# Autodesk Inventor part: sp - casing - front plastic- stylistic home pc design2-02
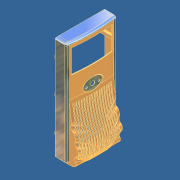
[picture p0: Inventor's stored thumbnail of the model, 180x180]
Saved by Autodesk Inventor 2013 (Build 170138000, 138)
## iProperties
Company: Autodesk Inc.
Created: 2005-12
Part Number: sp - casing - front plastic- stylistic home pc design2-02
Document SubType Name: Modeling
Designer: Autodesk Inc.
Stock Number: sp - casing - front plastic
Density: 1 g/cm^3
Mass: 300.417 g
Surface Area: 2156.89 cm^2
Volume: 300.417 cm^3
Material: Allgemein
Title: PC Demo
Author: Autodesk Inc.
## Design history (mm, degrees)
sketch "Sketch3"
  geometry: L1 (-90, 370)-(-79, 370); L2 (-79, 370)-(-79, 0); L3 (-79, 0)-(-90, 0); L4 (-90, 0)-(-90, 370); 2 further points
  constraints: 8 end point, 2 parallel, 1 coincident, 1 horizontal, 1 perpendicular
  dimensions: "d10" = 11 distance between parallel lines of L4 L2
extrude "Extrusion2" new body sketch "Sketch3" distance "d11" = 40; taper "d12" = 0 deg
mirror "Mirror1"
sketch "Sketch4"
  geometry: L1 (0, 11)-(40, 11) reference; L2 (0, 169)-(40, 169) reference; L3 (0, 169)-(0, 11); L4 (0, 180)-(40, 180) reference; L5 (40, 180)-(40, 169) reference; A1 r 600 centre (-554.776, 90) between (40, 11) and (40, 169)
  constraints: 2 end point, 2 point on circle, 1 centre point, 1 perpendicular
  dimensions: "d15" = 600 radius of A1
extrude "Extrusion3" join sketch "Sketch4" distance "d17" = 380 (computed from HEIGHT); taper "d18" = 0 deg
feature "FaceDraft7" dims angle "d20" = 10 deg
feature "FaceDraft8" dims angle "d21" = 10 deg
node "demo1"
sketch "Sketch10"
  geometry: L1 (203.5, 22.5)-(203.004, 22.434); L2 (203.004, 22.434)-(204.088, 14.307); L3 (204.088, -14.307)-(204.584, -14.373); L4 (206.5, 0)-(203.5, -22.5); L5 (204.584, -14.373)-(203.5, -22.5); L6 (203.004, -22.434)-(204.088, -14.307); L7 (203.5, -22.5)-(203.004, -22.434); L8 (204.584, 14.373)-(203.5, 22.5); L9 (204.088, 14.307)-(204.584, 14.373); L10 (206.5, 0)-(203.5, 22.5); C1 r 4 at (203.5, 22.5); C2 r 7.5 at (206.5, 0); C3 r 4 at (203.5, -22.5); C4 r 15 at (206.5, 0); A1 r 14.5 centre (206.5, 0) between (204.584, 14.373) and (204.584, -14.373)
  constraints: 20 end point, 5 centre point, 2 coincident, 2 point on circle, 2 point on line
workaxis "Work Axis1"
workplane "Work Plane4"
workplane "Work Plane5"
sketch "Sketch40"
  geometry: L1 (-45.224, 370)-(-45.224, -10) reference; L2 (-396, -52)-(0, -52) reference; L3 (-40, -10)-(-45.224, -10) reference; A1 r 333.146 centre (-378.319, 197.496) between (-69.011, 73.744) and (-45.224, 191.715); 1 further point
  constraints: 2 point on circle, 1 centre point, 1 horizontal, 1 point on line, 4 other
  dimensions: "d311" = 30.18241 horizontal distance of L1.end point (-75.406, 29.235); "d312" = 39.2354 vertical distance of L1.end point (-75.406, 29.235)
sketch "3D Sketch2"
  node "Project to Surface2"
sketch "3D Sketch3"
feature "SweepSrf2" dims "d255" = 0
feature "Extend3" dims "d256" = 80
feature "Extend4" dims "d257" = 80
feature "Sculpt2"
sketch "Sketch49" dims "d315" = 10
  geometry: L1 (191.715, 79)-(0, 79) reference; L2 (191.715, -79)-(0, -79) reference; L3 (-88.757, 0)-(446.459, 0) reference; 7 further points; 6 other entities
  constraints: 12 other
  dimensions: "d314" = 45 distance of point (108.452, 79) point (63.452, 79)
sketch "3D Sketch5"
  node "Project to Surface3"
sketch "Sketch50"
  geometry: A1 r 13.5 centre (57.483, 119.87) between (49.065, 130.425) and (55.768, 106.479); A2 r 14.055 centre (73.113, 75.347) between (63.316, 85.425) and (70.829, 61.479); A3 r 12.289 centre (71.124, 28.15) between (70.517, 40.425) and (67.276, 16.479); 1 further point
  constraints: 6 point on circle, 3 centre point
feature "Sculpt4"
feature "LoftSrf3" dims "d300" = 0, "d301" = 90 deg, "d302" = 0, "d303" = 90 deg
feature "LoftSrf4" dims "d304" = 0, "d305" = 90 deg, "d306" = 0, "d307" = 90 deg
feature "Sculpt5"
feature "Sculpt6"
mirror "Mirror6"
fillet "Fillet21" dims "d309" = 10
feature "FaceDraft12" dims angle "d281" = 2 deg
fillet "Fillet19" dims "d284" = 8
split "Split6"
shell "Shell7" dims "d279" = 3
fillet "Fillet20" dims "d286" = 5
sketch "Sketch11"
  geometry: L1 (-321.8, 0)-(485.3, 0) reference; L2 (0, -183.769)-(0, 183.769) reference; L3 (176.5, -2.5)-(11.5, -2.5); L4 (11.5, -2.5)-(11.5, -6.5); L5 (11.5, -6.5)-(176.5, -6.5); L6 (176.5, -6.5)-(176.5, -2.5); 2 further points
  constraints: 8 end point, 1 other
extrude "Extrusion14" cut sketch "Sketch11" distance "d114" = 375 (computed from HEIGHT); taper "d115" = 0 deg
pattern_linear "Rectangular Pattern4" dims "d118" = 9 (= 0.05 x WIDTH)
mirror "Mirror3"
workplane "Work Plane11"
sketch "Sketch14"
  geometry: L1 (308, 73)-(350, 73); L2 (350, 73)-(350, -73); L3 (350, -73)-(308, -73); L4 (308, -73)-(308, 73); L5 (370, 77.779)-(370, -77.779) reference; 2 further points
  constraints: 8 end point, 2 midpoint, 2 parallel, 1 horizontal, 1 horizontal alignment, 1 perpendicular
  dimensions: "d319" = 146 distance of L1.end L2.end; "d320" = 42 distance of L1.start L1.end; "d321" = 20 distance between parallel lines of L5 L2
extrude "Extrusion16" cut sketch "Sketch14" stored distance "d126" = 20; taper "d127" = 0 deg
pattern_linear "Rectangular Pattern5" dims "d130" = 42
feature "Sculpt3"
extrude "Extrusion18" cut sketch "Sketch10" stored distance "d168" = 10; taper "d169" = 0 deg
fillet "Fillet12" dims "d142" = 2
sketch "Sketch24"
  geometry: L1 (307.5, -87)-(297.5, -87); L2 (297.5, -87)-(297.5, -78.5); L3 (297.5, -78.5)-(307.5, -78.5); L4 (307.5, -78.5)-(307.5, -87); L5 (61, -87)-(71, -87); L6 (71, -87)-(71, -78.5); L7 (71, -78.5)-(61, -78.5); L8 (61, -78.5)-(61, -87); L9 (369, -89)-(369, 89); L10 (66, -78.5)-(66, -75.023); L11 (302.5, -78.5)-(302.5, -75.864); L12 (180, -87)-(190, -87); L13 (190, -87)-(190, -78.5); L14 (190, -78.5)-(180, -78.5); L15 (180, -78.5)-(180, -87); L16 (185, -78.5)-(185, -69.605); L17 (1, -47.752)-(1, -67.512); L18 (366.998, -87)-(3, -87); L19 (366.998, 87)-(366.998, 77.779) reference; L20 (366.998, 77.779)-(366.998, -77.779) reference; L21 (366.998, -77.779)-(366.998, -87) reference; L22 (366.998, -87)-(3, -87) reference; L23 (3, -87)-(3, -76) reference; L24 (3, -76)-(-7, -76) reference; L25 (-7, -76)-(-7, 76) reference; L26 (-7, 76)-(3, 76) reference; L27 (3, 76)-(3, 87) reference; L28 (3, 87)-(366.998, 87) reference; L29 (0, 79)-(0, 88) reference; L30 (0, 79)-(-10, 79) reference; L31 (-10, 79)-(-10, -79) reference; L32 (0, -79)-(-10, -79) reference; L33 (0, -79)-(0, -88) reference; L34 (2, -90)-(364.997, -90) reference; L35 (370, -77.779)-(370, -85) reference; L36 (370, 77.779)-(370, -77.779) reference; L37 (370, 85)-(370, 77.779) reference; L38 (2, 90)-(364.997, 90) reference; A1 r 2 centre (2, 88) between (2, 90) and (0, 88) reference; A2 r 2 centre (2, -88) between (0, -88) and (2, -90) reference; 2 further points
  constraints: 36 end point, 10 parallel, 5 midpoint, 3 equal length, 3 horizontal, 3 perpendicular, 2 horizontal alignment, 1 collinear, 2 other
  dimensions: "d188" = 368 distance between parallel lines of L9 L17 (derived); "d189" = 184 distance between parallel lines of L16 L17 (derived); "d190" = 10 distance of L2.end L3.end; "d191" = 8.5 distance of L12.end L13.end; "d194" = 65 distance from line of L10.end L17; "d195" = 66.5 distance between parallel lines of L11 L9
extrude "Extrusion21" join sketch "Sketch24" stored distance "d192" = 20; taper "d193" = 0 deg
mirror "Mirror4"
sketch "Sketch25"
  geometry: L1 (71, 176)-(71, 78.5) reference; L2 (190, 176)-(190, 78.5) reference; L3 (307.5, 176)-(307.5, 78.5) reference; L4 (297.5, 78.5)-(307.5, 78.5); L5 (307.5, 78.5)-(307.5, 82); L6 (307.5, 82)-(297.5, 82); L7 (297.5, 82)-(297.5, 78.5); L8 (180, 78.5)-(190, 78.5); L9 (190, 78.5)-(190, 82); L10 (190, 82)-(180, 82); L11 (180, 82)-(180, 78.5); L12 (61, 78.5)-(71, 78.5); L13 (71, 78.5)-(71, 82); L14 (71, 82)-(61, 82); L15 (61, 82)-(61, 78.5)
  constraints: 24 end point, 6 parallel, 3 horizontal, 3 perpendicular, 3 point on line, 2 collinear
  dimensions: "d197" = 3.5 distance between parallel lines of L4 L6
extrude "Extrusion22" join sketch "Sketch25" distance "d198" = 10; taper "d199" = 0 deg
sketch "Sketch32"
  geometry: L1 (307.5, 2)-(307.5, -78.5) reference; L2 (307.5, -78.5)-(297.5, -78.5) reference; L3 (190, 2)-(190, -78.5) reference; L4 (71, 2)-(71, -78.5) reference; L5 (297.5, -78.5)-(307.5, -78.5); L6 (307.5, -78.5)-(307.5, -82); L7 (307.5, -82)-(297.5, -82); L8 (297.5, -82)-(297.5, -78.5); L9 (180, -78.5)-(190, -78.5); L10 (190, -78.5)-(190, -82); L11 (190, -82)-(180, -82); L12 (180, -82)-(180, -78.5); L13 (61, -78.5)-(71, -78.5); L14 (71, -78.5)-(71, -82); L15 (71, -82)-(61, -82); L16 (61, -82)-(61, -78.5)
  constraints: 24 end point, 6 parallel, 3 horizontal, 3 perpendicular, 3 point on line, 2 collinear
  dimensions: "d222" = 3.5 distance between parallel lines of L2 L7
extrude "Extrusion29" join sketch "Sketch32" distance "d223" = 10; taper "d224" = 0 deg
body "Solid1"
sketch "Sketch19"
  geometry: L1 (-94.857, 206.5)-(15.809, 206.5) reference; L2 (0, 0)-(0, 370) reference; A1 r 40 centre (-79.047, 206.5) between (-50, 179) and (-50, 234)
  constraints: 2 point on circle, 1 centre point, 1 symmetric about line
  dimensions: "d152" = 55 distance of A1.start A1.end; "d153" = 50 distance from line of L2 A1.end; "d154" = 40 radius of A1
sketch "Sketch20"
  geometry: L1 (0, 0)-(0, 370) reference; L2 (-94.8, 206.5)-(15.8, 206.5) reference; A1 r 30 centre (-76.367, 206.5) between (-52, 189) and (-52, 224)
  constraints: 2 point on circle, 1 centre point, 1 symmetric about line
  dimensions: "d156" = 52 distance from line of L1 A1.end; "d157" = 35 distance of A1.end A1.start; "d158" = 30 radius of A1
sketch "Sketch41"
  geometry: L1 (370, -79)-(0, -79) reference; L2 (370, 79)-(0, 79) reference; L3 (191.715, -79)-(191.715, 79); 1 further point
  constraints: 2 end point, 2 point on line, 1 perpendicular
  dimensions: "d313" = 191.71483 distance from line of L1.end L3
sketch "Sketch21"
  geometry: A1 r 30 centre (-76.367, 206.5) between (-52, 189) and (-52, 224) reference
body "Srf7"
body "Srf8"
body "Srf1"
sketch "Sketch43"
  geometry: L1 (0, 11)-(-40, 11) reference; L2 (0, 169)-(0, 11) reference; L3 (10.614, 11)-(-113.917, 11)
  constraints: 2 end point, 1 perpendicular
body "Srf2"
sketch "Sketch44"
  geometry: L1 (-40, 169)-(0, 169) reference; L2 (0, 169)-(0, 11) reference; L3 (6.47, 169)-(-88.359, 169)
  constraints: 2 end point, 1 perpendicular
body "Srf3"
sketch "Sketch47"
  geometry: L1 (370, 90)-(370, -90) reference; L2 (0, -90)-(370, -90) reference; L3 (368.87, 77.779)-(398.87, 77.779); L4 (398.87, 77.779)-(398.87, -77.779); L5 (398.87, -77.779)-(368.87, -77.779)
  constraints: 6 end point, 2 parallel, 1 perpendicular
  dimensions: "d285" = 30 distance of L3.start L3.end
body "Srf4"
body "Srf5"
body "Srf6"
feature "LoftSrf1" dims "d160" = 0, "d161" = 90 deg, "d162" = 0, "d163" = 90 deg, "d164" = 0, "d165" = 90 deg
feature "OffsetSrf1" dims "d166" = 1, "d167" = 2
extrude_surface "ExtrusionSrf2" dims "d258" = 277.75, "d259" = 0
extrude_surface "ExtrusionSrf3" dims "d260" = 277.75, "d261" = 0
feature "LoftSrf2" dims "d296" = 0, "d297" = 90 deg, "d298" = 0, "d299" = 90 deg
other parameters: "d16" = 142 [user parameter], "d89" = 0.5, "d155" = -45, "d159" = 45, "d310" = -79, "d318" = 0
